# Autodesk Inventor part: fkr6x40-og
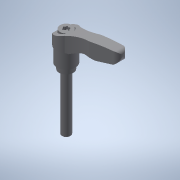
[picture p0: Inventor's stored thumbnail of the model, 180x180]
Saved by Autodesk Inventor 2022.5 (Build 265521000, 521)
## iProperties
Created: 2017-09
Part Number: fkr6x40-og
Material: 一般
Document SubType Name: Modeling
Designer: imaocorp
Density: 1 g/cm^3
Appearance: 既定
Author: imaocorp
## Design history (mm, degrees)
node "fkr6x40-og.x_t1"
node "fkr6x40-og"
node "Base1"
